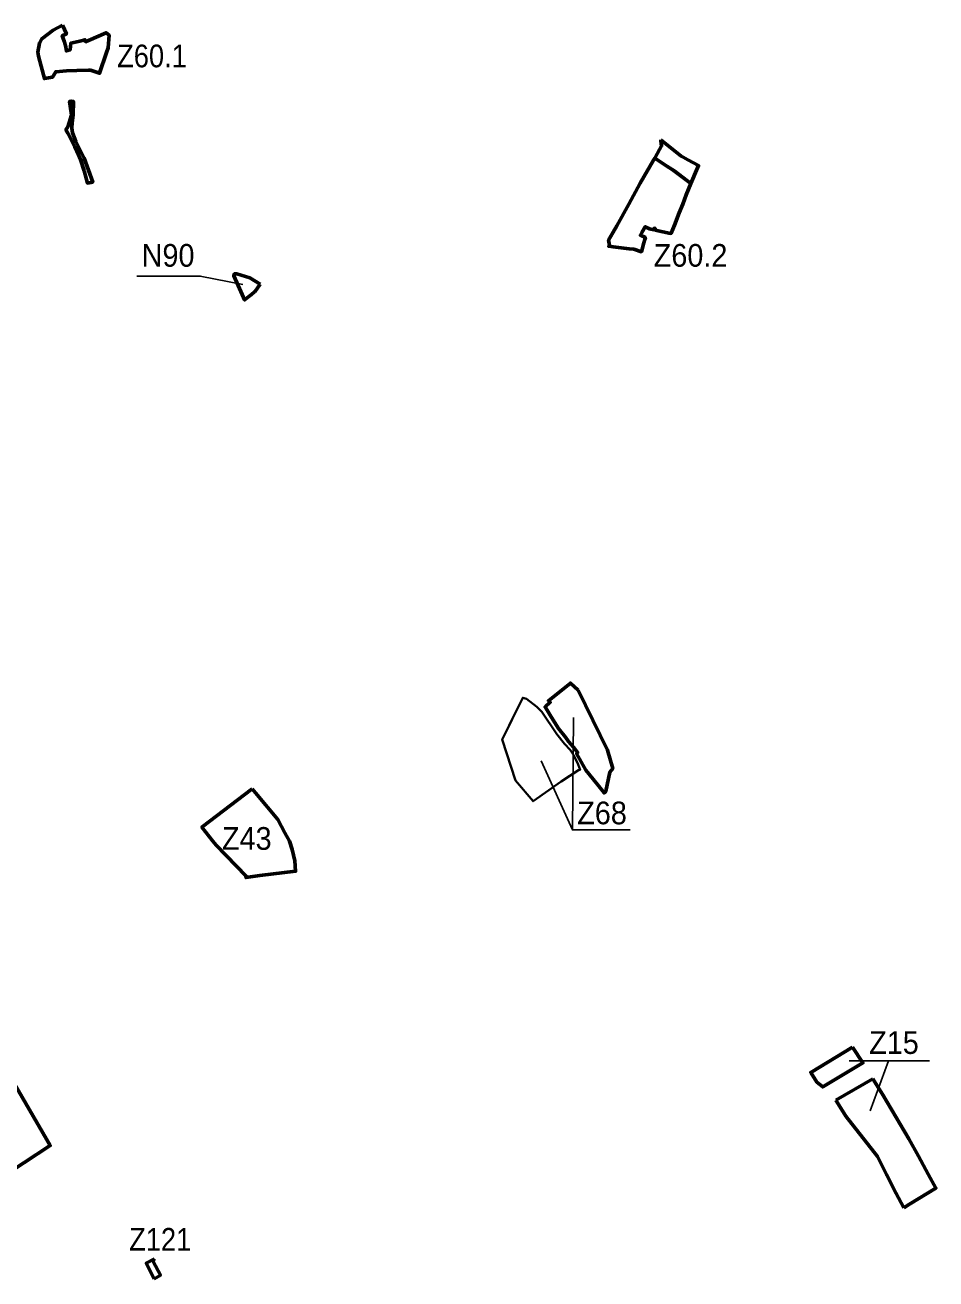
# Model space of a CAD drawing. Extents: x -650277 to -643425, y -1073980 to -1066720.
# Drawn here: x -647467 to -646503, y -1071700 to -1070373 of the extents above; entities that cross this region are included whole.
import ezdxf

# ---------------------------------------------------------------- set-up
doc = ezdxf.new("R2010")
doc.units = 0
doc.header["$LTSCALE"] = 9.6
for name, color, linetype, lineweight in [('1', 7, 'Continuous', 60), ('15', 7, 'Continuous', 60), ('17', 7, 'Continuous', 60), ('2', 7, 'Continuous', 40), ('59', 7, 'Continuous', 25), ('63', 7, 'Continuous', 25), ('9', 7, 'Continuous', 60)]:
    doc.layers.add(name, color=color, linetype=linetype, lineweight=lineweight)

msp = doc.modelspace()

# ---------------------------------------------------------------- linework, layer by layer
at = {"layer": '1'}
msp.add_line((-646609.21, -1071510.98), (-646570, -1071488.38), dxfattribs=at)
msp.add_lwpolyline([(-646591.65, -1071454.91), (-646635.79, -1071481.6), (-646629.37, -1071491.74), (-646623.18, -1071496.99), (-646580.58, -1071471.48)], close=True, dxfattribs=at)
for points in [[(-646570, -1071488.38), (-646559.53, -1071505.12), (-646550.23, -1071520.88), (-646541.14, -1071536.3), (-646532.04, -1071551.72), (-646521.8, -1071570.34), (-646511.47, -1071589.11), (-646503.31, -1071603.95), (-646531.2, -1071621.07), (-646537.28, -1071624.8)], [(-646537.28, -1071624.8), (-646545.89, -1071609.07), (-646555.78, -1071589.66), (-646565.17, -1071570.4), (-646598.63, -1071527.8), (-646609.21, -1071510.98)]]:
    msp.add_lwpolyline(points, dxfattribs=at)
at = {"layer": '1', "lineweight": 53}
for points in [[(-647330.34, -1071678.82), (-647339.211, -1071683.431), (-647330.73, -1071700.09)], [(-647330.73, -1071700.09), (-647324.21, -1071696.2), (-647331.65, -1071681.7), (-647330.34, -1071678.82)]]:
    msp.add_lwpolyline(points, dxfattribs=at)
at = {"layer": '15'}
msp.add_lwpolyline([(-647404.96, -1070527.57), (-647401.35, -1070540.59), (-647395.75, -1070539.47), (-647404.879, -1070514.114), (-647413.552, -1070496.671), (-647417.297, -1070487.185), (-647418.038, -1070482.516), (-647417.482, -1070476.846), (-647416.37, -1070468.064), (-647416.148, -1070454.055), (-647418.49, -1070453.76), (-647420.13, -1070454.78), (-647420.22, -1070454.02), (-647418.41, -1070468.21), (-647420.74, -1070476.57), (-647422.285, -1070480.931), (-647424.226, -1070484.029), (-647422.19, -1070487.75), (-647414.6, -1070502.16), (-647410.86, -1070510.68), (-647408.82, -1070515.49)], close=True, dxfattribs=at)
for points in [[(-646794.59, -1070494.62), (-646794.53, -1070495.7), (-646793.75, -1070501.26), (-646800.6, -1070513.43), (-646800.94, -1070514.04)], [(-646755.84, -1070524.5), (-646754.52, -1070522.08), (-646765.96, -1070515.75), (-646770.95, -1070512.94), (-646773, -1070511.96), (-646794.59, -1070494.62)], [(-646800.94, -1070514.04), (-646788, -1070522.49), (-646782.63, -1070526.02)], [(-646782.63, -1070526.02), (-646779.68, -1070527.87), (-646762.71, -1070540.85), (-646755.84, -1070524.5)]]:
    msp.add_lwpolyline(points, dxfattribs=at)
at = {"layer": '17'}
msp.add_lwpolyline([(-647427.8, -1070373.32), (-647437.76, -1070378.66), (-647449.69, -1070387.83), (-647452.17, -1070392.38), (-647453.71, -1070401.81), (-647453.35, -1070406.09), (-647450.51, -1070416.96), (-647446.93, -1070429.99), (-647438.45, -1070428.47), (-647434.85, -1070422.64), (-647423.38, -1070421.87), (-647412.51, -1070421.5), (-647400.41, -1070421.08), (-647398.21, -1070421.15), (-647388.6, -1070424.24), (-647381.11, -1070402.45), (-647379.3, -1070397.57), (-647378.49, -1070383.91), (-647381.65, -1070381.45), (-647400.22, -1070389.64), (-647403.27, -1070390.91), (-647404, -1070388.84), (-647409.36, -1070390.24), (-647419.08, -1070392.52), (-647419.68, -1070399.59), (-647423.58, -1070400.59), (-647424.54, -1070394.78), (-647425.99, -1070390.47), (-647427.96, -1070384.64), (-647423.57, -1070382.64)], close=True, dxfattribs=at)
msp.add_lwpolyline([(-647427.8, -1070373.32), (-647437.76, -1070378.66), (-647449.69, -1070387.83), (-647452.17, -1070392.38), (-647453.71, -1070401.81), (-647453.35, -1070406.09), (-647450.51, -1070416.96), (-647446.93, -1070429.99), (-647438.45, -1070428.47), (-647434.85, -1070422.64), (-647423.38, -1070421.87), (-647412.51, -1070421.5), (-647400.41, -1070421.08), (-647398.21, -1070421.15), (-647388.6, -1070424.24), (-647381.11, -1070402.45), (-647379.3, -1070397.57), (-647378.49, -1070383.91), (-647381.65, -1070381.45), (-647400.22, -1070389.64), (-647403.27, -1070390.91), (-647404, -1070388.84), (-647409.36, -1070390.24), (-647419.08, -1070392.52), (-647419.68, -1070399.59), (-647423.58, -1070400.59), (-647424.54, -1070394.78), (-647425.99, -1070390.47), (-647427.96, -1070384.64), (-647423.57, -1070382.64)], close=True, dxfattribs=at)
at = {"layer": '2', "lineweight": 60}
for points in [[(-647218.44, -1070647.43), (-647229.34, -1070640.91), (-647243.28, -1070636.43), (-647245.6, -1070636.4), (-647246.49, -1070638.53), (-647241.89, -1070648.94)], [(-647241.89, -1070648.94), (-647237.61, -1070658.33), (-647235.02, -1070664.1), (-647227.76, -1070658.33)], [(-647227.76, -1070658.33), (-647224.57, -1070655.48), (-647224.37, -1070655.59), (-647218.44, -1070647.43)]]:
    msp.add_lwpolyline(points, dxfattribs=at)
at = {"layer": '2', "lineweight": 25}
msp.add_lwpolyline([(-647349, -1070639), (-647282, -1070639), (-647237, -1070648)], dxfattribs=at)
at = {"layer": '2'}
msp.add_lwpolyline([(-646921.668, -1071098.861), (-646920.54, -1071099.98), (-646904.64, -1071123.54), (-646896.62, -1071133.93), (-646890.59, -1071140.39), (-646887.07, -1071145.66), (-646881.97, -1071155.84), (-646879.91, -1071161.24), (-646881.68, -1071161.83), (-646899.85, -1071173.89), (-646929.64, -1071194.58), (-646948.286, -1071172.534), (-646962.471, -1071129.325), (-646955.138, -1071114.466), (-646951.831, -1071107.765), (-646951.831, -1071107.765), (-646940.67, -1071085.15), (-646940.67, -1071085.15), (-646936.51, -1071086.33), (-646925.88, -1071094.68)], close=True, dxfattribs=at)
at = {"layer": '59'}
msp.add_lwpolyline([(-646827, -1071225), (-646888, -1071225), (-646921, -1071152)], dxfattribs=at)
at = {"layer": '63'}
for p, q in [((-646887, -1071106), (-646888, -1071225)), ((-646510.087, -1071469.269), (-646595.257, -1071469.269)), ((-646572.844, -1071522.353), (-646553.419, -1071469.269))]:
    msp.add_line(p, q, dxfattribs=at)
at = {"layer": '9'}
for points in [[(-646802.19, -1070516.26), (-646816.42, -1070540.49), (-646828.45, -1070562.89), (-646841.16, -1070585.79), (-646844.76, -1070592.54), (-646849.72, -1070600.98), (-646848.99, -1070606.28), (-646849.59, -1070607.4), (-646844.96, -1070607.98), (-646827.88, -1070610.12), (-646822.99, -1070610.51), (-646815.05, -1070613.14), (-646812.5, -1070603.78), (-646811.5, -1070600.29), (-646810.82, -1070598.23), (-646816.11, -1070595.8), (-646814.52, -1070592.78), (-646811.06, -1070586.67), (-646806.41, -1070589), (-646802.06, -1070589.93), (-646801.73, -1070588.37), (-646800.13, -1070588.71), (-646800.47, -1070590.28), (-646784.18, -1070593.76), (-646784, -1070593.34), (-646783.59, -1070593.52), (-646779.9, -1070584.92), (-646774.91, -1070571.88), (-646771.17, -1070562.7), (-646767.63, -1070553.09), (-646762.71, -1070540.85), (-646782.63, -1070526.02), (-646788, -1070522.49), (-646800.94, -1070514.04)], [(-646881.89, -1071077.03), (-646890.12, -1071069.67), (-646913.49, -1071088.22), (-646911.58, -1071089.9), (-646917.04, -1071094.75), (-646910.53, -1071105.18), (-646902.62, -1071117.58), (-646895.56, -1071126.84), (-646892.339, -1071131.481), (-646886.78, -1071137.25), (-646882.37, -1071143.39), (-646883.63, -1071144.15), (-646873.89, -1071161.58), (-646861.58, -1071177.05), (-646854.49, -1071185.87), (-646852.86, -1071183.98), (-646848.58, -1071163.95), (-646845.39, -1071159.98), (-646850.93, -1071140.54)], [(-647226.895, -1071181.511), (-647280.14, -1071221.92), (-647268.52, -1071236.78), (-647265.15, -1071241.1), (-647233.34, -1071274.07), (-647233.64, -1071275.42), (-647218.75, -1071273.32), (-647181.12, -1071268.66), (-647181.99, -1071257.66), (-647184.58, -1071245.67), (-647187.68, -1071236.74), (-647192.29, -1071228.1), (-647199.82, -1071213.98), (-647223.46, -1071185.83)], [(-647497.04, -1071595.66), (-647440.67, -1071558.93), (-647492.3, -1071470), (-647495.85, -1071471.06), (-647558.654, -1071489.738)]]:
    msp.add_lwpolyline(points, close=True, dxfattribs=at)

# ---------------------------------------------------------------- texts
at = {"layer": '59', "width": 0.95}
for s, p in [('N90', (-647344, -1070629)), ('Z68', (-646883, -1071219))]:
    msp.add_text(s, height=24, dxfattribs=at).set_placement(p)
at = {"layer": '63'}
for s, width, p in [('Z60.1', 0.9, (-647370, -1070418)), ('Z60.2', 0.95, (-646802, -1070629)), ('Z43', 0.95, (-647259, -1071246)), ('Z15', 0.95, (-646574, -1071462)), ('Z121', 0.9, (-647357.291, -1071670.187))]:
    msp.add_text(s, height=24, dxfattribs=dict(at, width=width)).set_placement(p)

doc.saveas('drawing.dxf')
